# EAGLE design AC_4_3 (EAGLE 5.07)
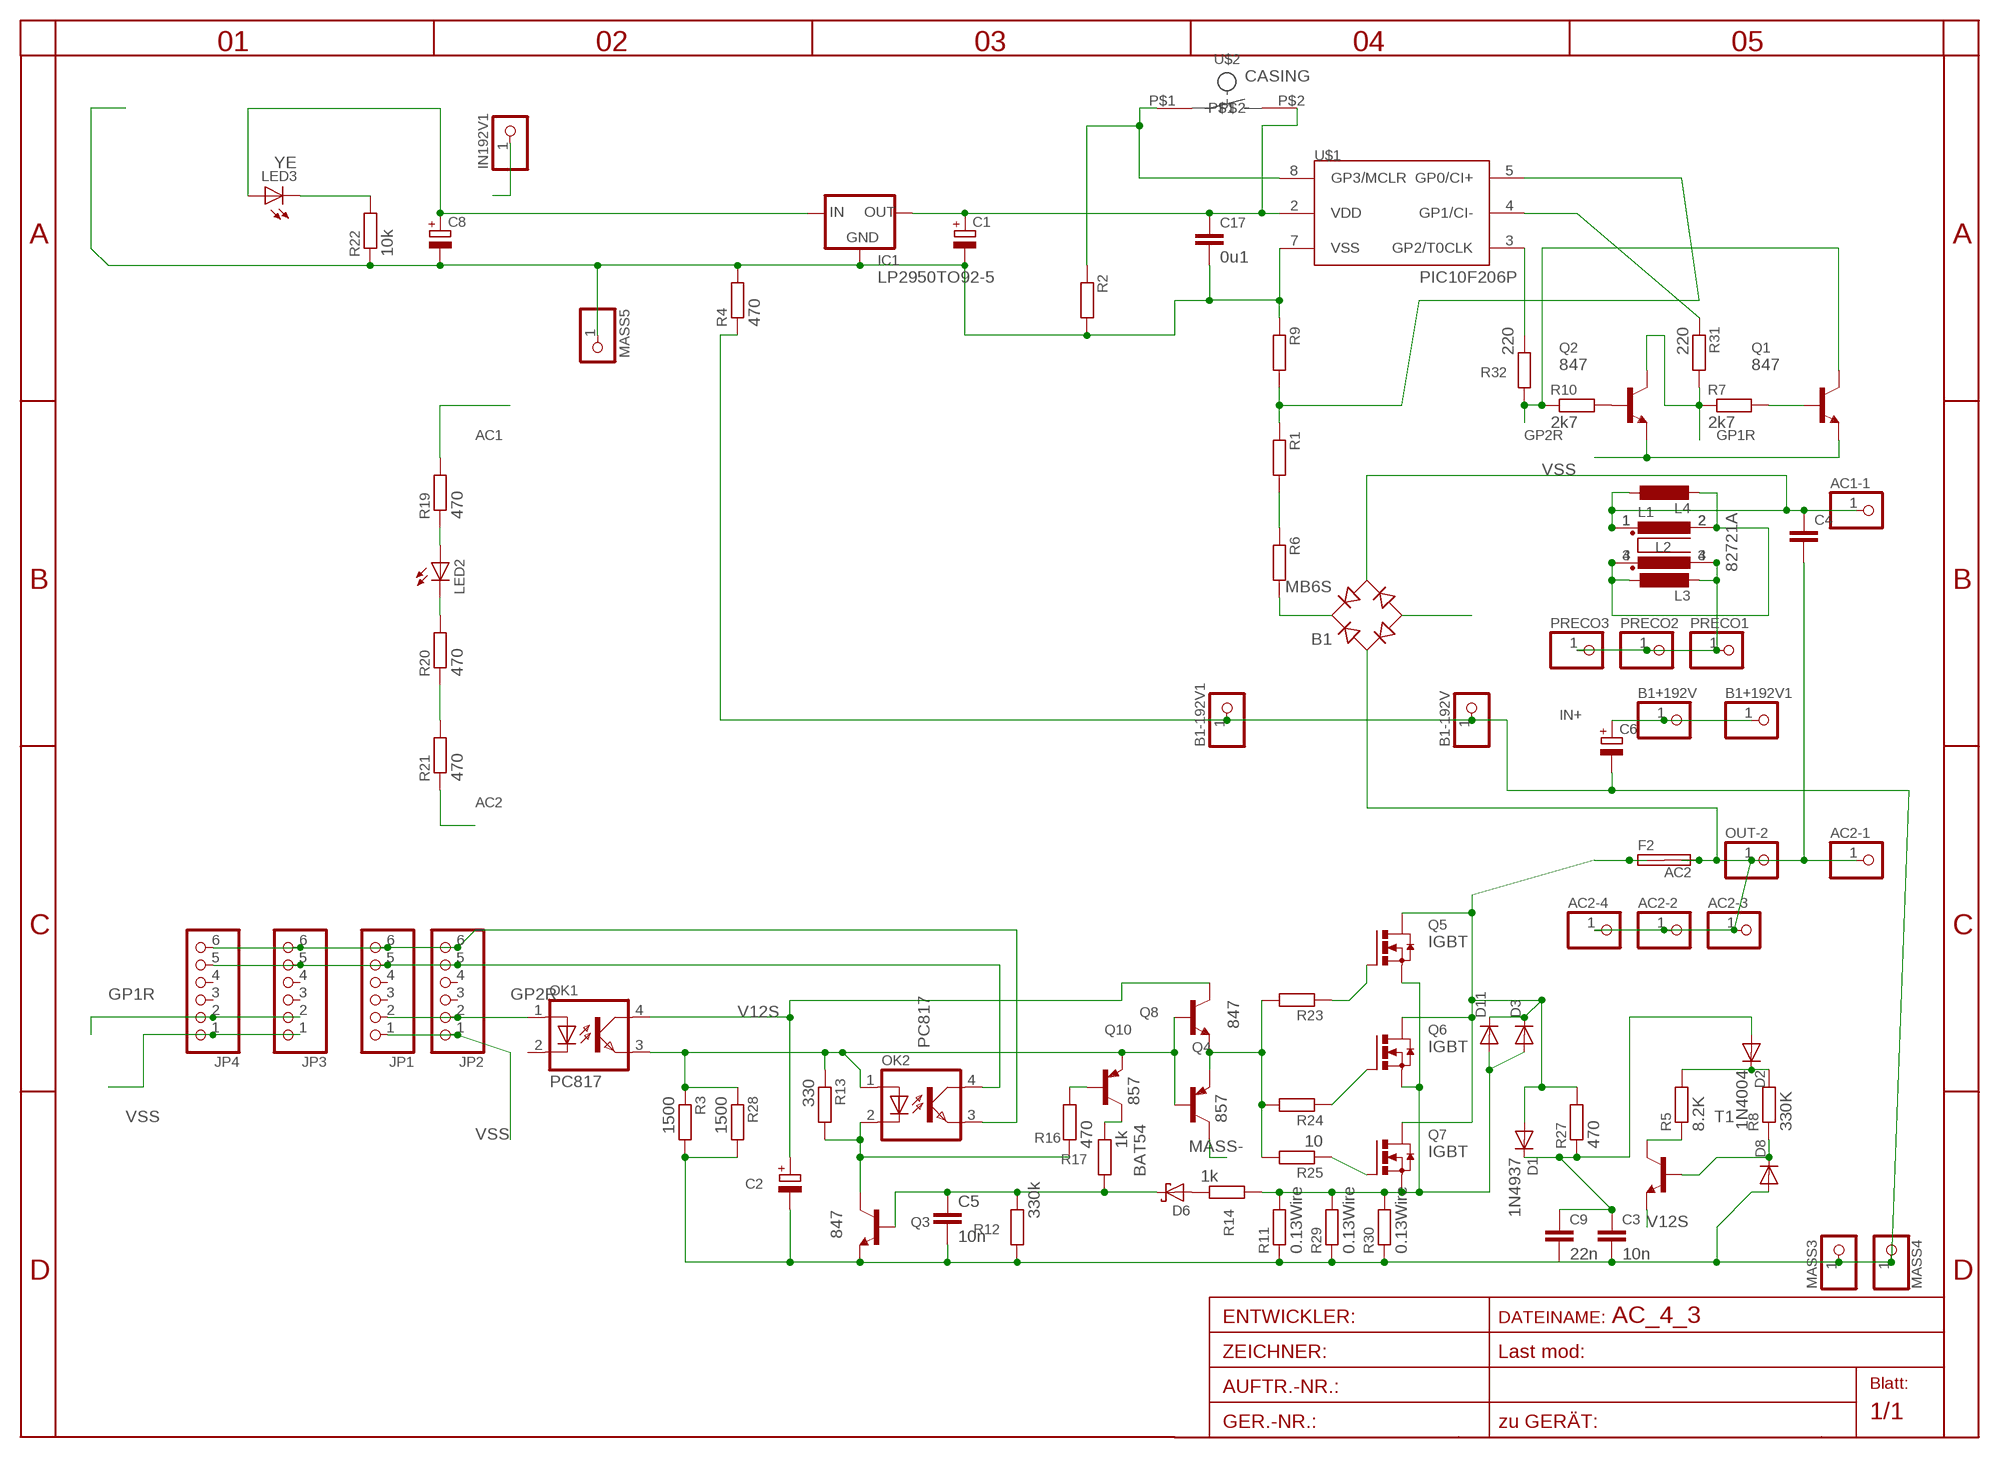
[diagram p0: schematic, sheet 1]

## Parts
AC1-1  PINHD-1X14.5MM  [1X4MM5]
AC2-1  PINHD-1X14.5MM  [1X4MM5]
AC2-2  PINHD-1X13MM2  [1X3MM2]
AC2-3  PINHD-1X13MM2  [1X3MM2]
AC2-4  PINHD-1X12MM3  [1X2MM3]
B1  MB6S  [SOIC-4]
B1+192V  PINHD-1X13MM2  [1X3MM2]
B1+192V1  PINHD-1X13MM2  [1X3MM2]
B1-192V  PINHD-1X13MM2  [1X3MM2]
B1-192V1  PINHD-1X13MM2  [1X3MM2]
C1  CPOL-EUE5-6  [E5-6]
C2  CPOL-EUE2.5-5  [E2,5-5]
C3  10n  C-EU025_050-050X075  [C025_050-050X075]
C4  C-EU225-108X268  [C225-108X268]
C5  10n  C-EUC0805  [C0805]
C6  CPOL-EUE10-20  [EB20D]
C8  CPOL-EUE5-5  [E5-5]
C9  22n  C-EU102-043X133  [C102-043X133]
C17  0u1  C-EUC1206  [C1206]
D1  1N4937  1N4004DO41-10  [DO41-10]
D2  1N4004  [DO41-20]
D3  DIODE-SMC  [SMC]
D6  BAT54  [SOT23]
D8  DIODE-MINIMELF  [MINIMELF]
D11  DIODE-SMC  [SMC]
F2  SHK20L7MM5  [7MM5]
IC1  LP2950TO92-5  [T092-5]
IN192V1  PINHD-1X13MM2  [1X3MM2]
JP1  PINHD-1X6  [1X06BOX]
JP2  PINHD-1X6  [1X06BOX]
JP3  PINHD-1X6  [1X06BOX]
JP4  PINHD-1X6  [1X06BOX]
L1  R1405VB1  [B1]
L2  82721A  [82721A]
L3  L-EU2200-15.24  [2200-15.24]
L4  L-EU2200-15.24  [2200-15.24]
LED2  LED3MM  [LED3MM]
LED3  YE  LEDCHIPLED_1206  [CHIPLED_1206]
MASS3  PINHD-1X13MM2  [1X3MM2]
MASS4  PINHD-1X13MM2  [1X3MM2]
MASS5  PINHD-1X11MM6  [1X1MM8]
OK1  PC817  [DIL04]
OK2  PC817  [DIL04]
OUT-2  PINHD-1X13MM2  [1X3MM2]
PRECO1  PINHD-1X12MM3  [1X2MM3]
PRECO2  PINHD-1X13MM2  [1X3MM2]
PRECO3  PINHD-1X13MM2  [1X3MM2]
Q1  847  BC847ALT1SMD  [SOT23]
Q2  847  BC847ALT1SMD  [SOT23]
Q3  847  BC846ALT1SMD  [SOT23]
Q4  857  BC857ALT1SMD  [SOT23-BEC]
Q5  IGBT  N-HEXFET_DPAK-  [TO252]
Q6  IGBT  N-HEXFET_DPAK-  [TO252]
Q7  IGBT  N-HEXFET_DPAK-  [TO252]
Q8  847  BC846ALT1SMD  [SOT23]
Q10  857  BC857ALT1SMD  [SOT23-BEC]
R1  R-EU_0207/30  [0207/30]
R2  R-EU_R0805  [R0805]
R3  1500  R-EU_R0805  [R0805]
R4  470  R-EU_0204/5  [0204/5]
R5  8.2K  R-EU_0204/5  [0204/5]
R6  R-EU_0207/50  [0207/50]
R7  2k7  R-EU_R0805  [R0805]
R8  330K  R-EU_0204/5  [0204/5]
R9  R-EU_R0805  [R0805]
R10  2k7  R-EU_R0805  [R0805]
R11  0.13Wire  R-EU_0204/5  [0204/5]
R12  330k  R-EU_R0805  [R0805]
R13  330  R-EU_R1206  [R1206]
R14  1k  R-EU_R0805  [R0805]
R16  470  R-EU_R0805  [R0805]
R17  1k  R-EU_R0805  [R0805]
R19  470  R-EU_0204/5  [0204/5]
R20  470  R-EU_0204/2V  [0204V]
R21  470  R-EU_0204/5  [0204/5]
R22  10k  R-EU_R1206  [R1206]
R23  R-EU_0207/15  [0207/15]
R24  R-EU_0207/10  [0207/10]
R25  10  R-EU_0207/15  [0207/15]
R27  470  R-EU_0207/10  [0207/10]
R28  1500  R-EU_R1206  [R1206]
R29  0.13Wire  R-EU_0204/5  [0204/5]
R30  0.13Wire  R-EU_0204/5  [0204/5]
R31  220  R-EU_R1206  [R1206]
R32  220  R-EU_R1206  [R1206]
T1  -NPN-TO92-EBC  [TO92-EBC]
U$1  PIC10F206P  [DIL8]
U$2  CASING  [CASING]

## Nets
AC1: AC1-1.1 B1.~2(AC2) C4.1 L1.1 L2.1 L4.1 R19.2
AC2: AC2-1.1 AC2-2.1 AC2-3.1 AC2-4.1 B1.~1(AC1) C4.2 F2.2A F2.2B OUT-2.1 R21.1
BATT+: C8.+ IC1.3(IN) LED3.A
D1: D1.A D3.C D11.C F2.1A F2.1B Q5.3(D) Q6.3(D) Q7.3(D) R27.2
GP1R: JP3.2 JP4.2 Q2.3(C) R7.1 R31.2
GP2R: JP1.2 JP2.2 OK1.1(A) Q1.3(C) R10.1 R32.2
GP3: JP1.6 JP2.6 JP3.6 JP4.6 OK2.3(EMIT) R2.1 U$1.8(GP3/MCLR) U$2.P$1
IN+: B1+192V1.1 B1+192V.1 C6.+ IN192V1.1
INN: L1.2 L1.3 L2.2 L2.4 L3.1 L4.2
MASS-: B1-192V1.1 B1-192V.1 B1.- C2.- C3.3 C5.2 C6.- C9.2 D8.A MASS3.1 MASS4.1 Q3.2(E) Q4.C R3.2 R4.1 R11.1 R12.2 R28.2 R29.1 R30.1
N$1: R1.1 R9.2 U$1.5(GP0/CI+)
N$2: C3.1 C9.1 D1.C D2.A R27.1
N$3: R1.2 R6.1
N$4: Q2.1(B) R10.2
N$6: LED2.A R19.1
N$7: Q1.1(B) R7.2
N$9: LED2.K(C) R20.2
N$11: C5.1 D6.3(C) Q3.1(B) R12.1 R17.2
N$12: OK2.2(C) Q3.3(C) R13.2 R16.1
N$13: R20.1 R21.2
N$14: D6.1(A) R14.1
N$15: LED3.C R22.2
N$16: Q10.B R16.2
N$17: Q10.C R17.1
N$20: D2.C R5.2 R8.2
N$25: Q7.1(G) R25.1
N$26: Q6.1(G) R24.1
N$27: Q5.1(G) R23.1
N$33: B1.+ R6.2
N$34: R5.1 T1.C
N$36: D8.C R8.1 T1.B
N$37: Q4.E Q8.2(E) R23.2 R24.2 R25.2
N$39: R31.1 U$1.4(GP1/CI-)
N$43: R32.1 U$1.3(GP2/T0CLK)
PP1: OK1.3(EMIT) OK2.1(A) Q4.B Q8.1(B) Q10.E R3.1 R13.1 R28.1
PRECOIL: L1.4 L2.3 L3.2 PRECO1.1 PRECO2.1 PRECO3.1
SRC1: D3.A D11.A Q5.2(S) Q6.2(S) Q7.2(S) R11.2 R14.2 R29.2 R30.2
V12S: C2.+ OK1.4(COL) Q8.3(C) T1.E
VDD: C1.+ C17.1 IC1.1(OUT) JP1.5 JP2.5 JP3.5 JP4.5 OK2.4(COL) U$1.2(VDD) U$2.P$2
VSS: C1.- C8.- C17.2 IC1.2(GND) JP1.1 JP2.1 JP3.1 JP4.1 MASS5.1 Q1.2(E) Q2.2(E) R2.2 R4.2 R9.1 R22.1 U$1.7(VSS)
Unconnected: JP1.3 JP1.4 JP2.3 JP2.4 JP3.3 JP3.4 JP4.3 JP4.4 OK1.2(C)

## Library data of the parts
AC1-1 AC2-1-AC2-4 B1+192V B1+192V1 B1-192V B1-192V1 IN192V1 MASS3-MASS5 OUT-2 PRECO1-PRECO3 = pinhead:PINHD-1X1: PIN HEADER
B1 = rectifier:MB*S: Bridge Rectifier Source: http://www.fairchildsemi.com/ds/MB/MB6S.pdf
C1 C2 C8 = rcl-2:CPOL-EU: POLARIZED CAPACITOR, European symbol
C3 C9 C17 = rcl-2:C-EU: CAPACITOR, European symbol
C4 C5 = rcl:C-EU: CAPACITOR, European symbol
C6 = rcl:CPOL-EU: POLARIZED CAPACITOR, European symbol
D1 D2 = diode:1N4004: DIODE
D3 D8 D11 = diode:DIODE-: DIODE
D6 = diode:BAT54: Schottky Diodes
F2 = fuse:SHK20L: FUSE HOLDER 5 x 20 mm, SH contact, SHH1 Schukat, E1073 Buerklin
IC1 = v-reg:LP2950?*: Source: http://cache.national.com/ds/LP/LP2950.pdf
JP1-JP4 = pinhead:PINHD-1X6: PIN HEADER
L1 = inductor-nkl:R1405V: Übertrager (verlustarm) bis typ. 400kHz Power transformer (low loss) up to typ. 400kHz
L2 = inductors:82721A: FILTER
L3 L4 = rcl:L-EU: INDUCTOR, European symbol
LED2 LED3 = led:LED: LED
OK1 OK2 = optocoupler:PC817: SHARP OPTO COUPLER
Q1 Q2 = transistor-npn:BC847*: NPN Transistor
Q3 Q8 = transistor-npn:BC846*: NPN Transistor
Q4 Q10 = transistor-pnp:BC857*: PNP Transistror
Q5-Q7 = transistor-power:N-HEXFET_?-*: HEXFET® Power MOSFET
R1-R14 R16 R17 R19-R25 R27-R32 = rcl-2:R-EU_: RESISTOR, European symbol
T1 = transistor-neu-to92:*-NPN-: NPN Transistror
U$1 = microchip-5:PIC10F2*: uPC nW 0,25/0,5k Program Flash memory Comparator
U$2 = button:CASING

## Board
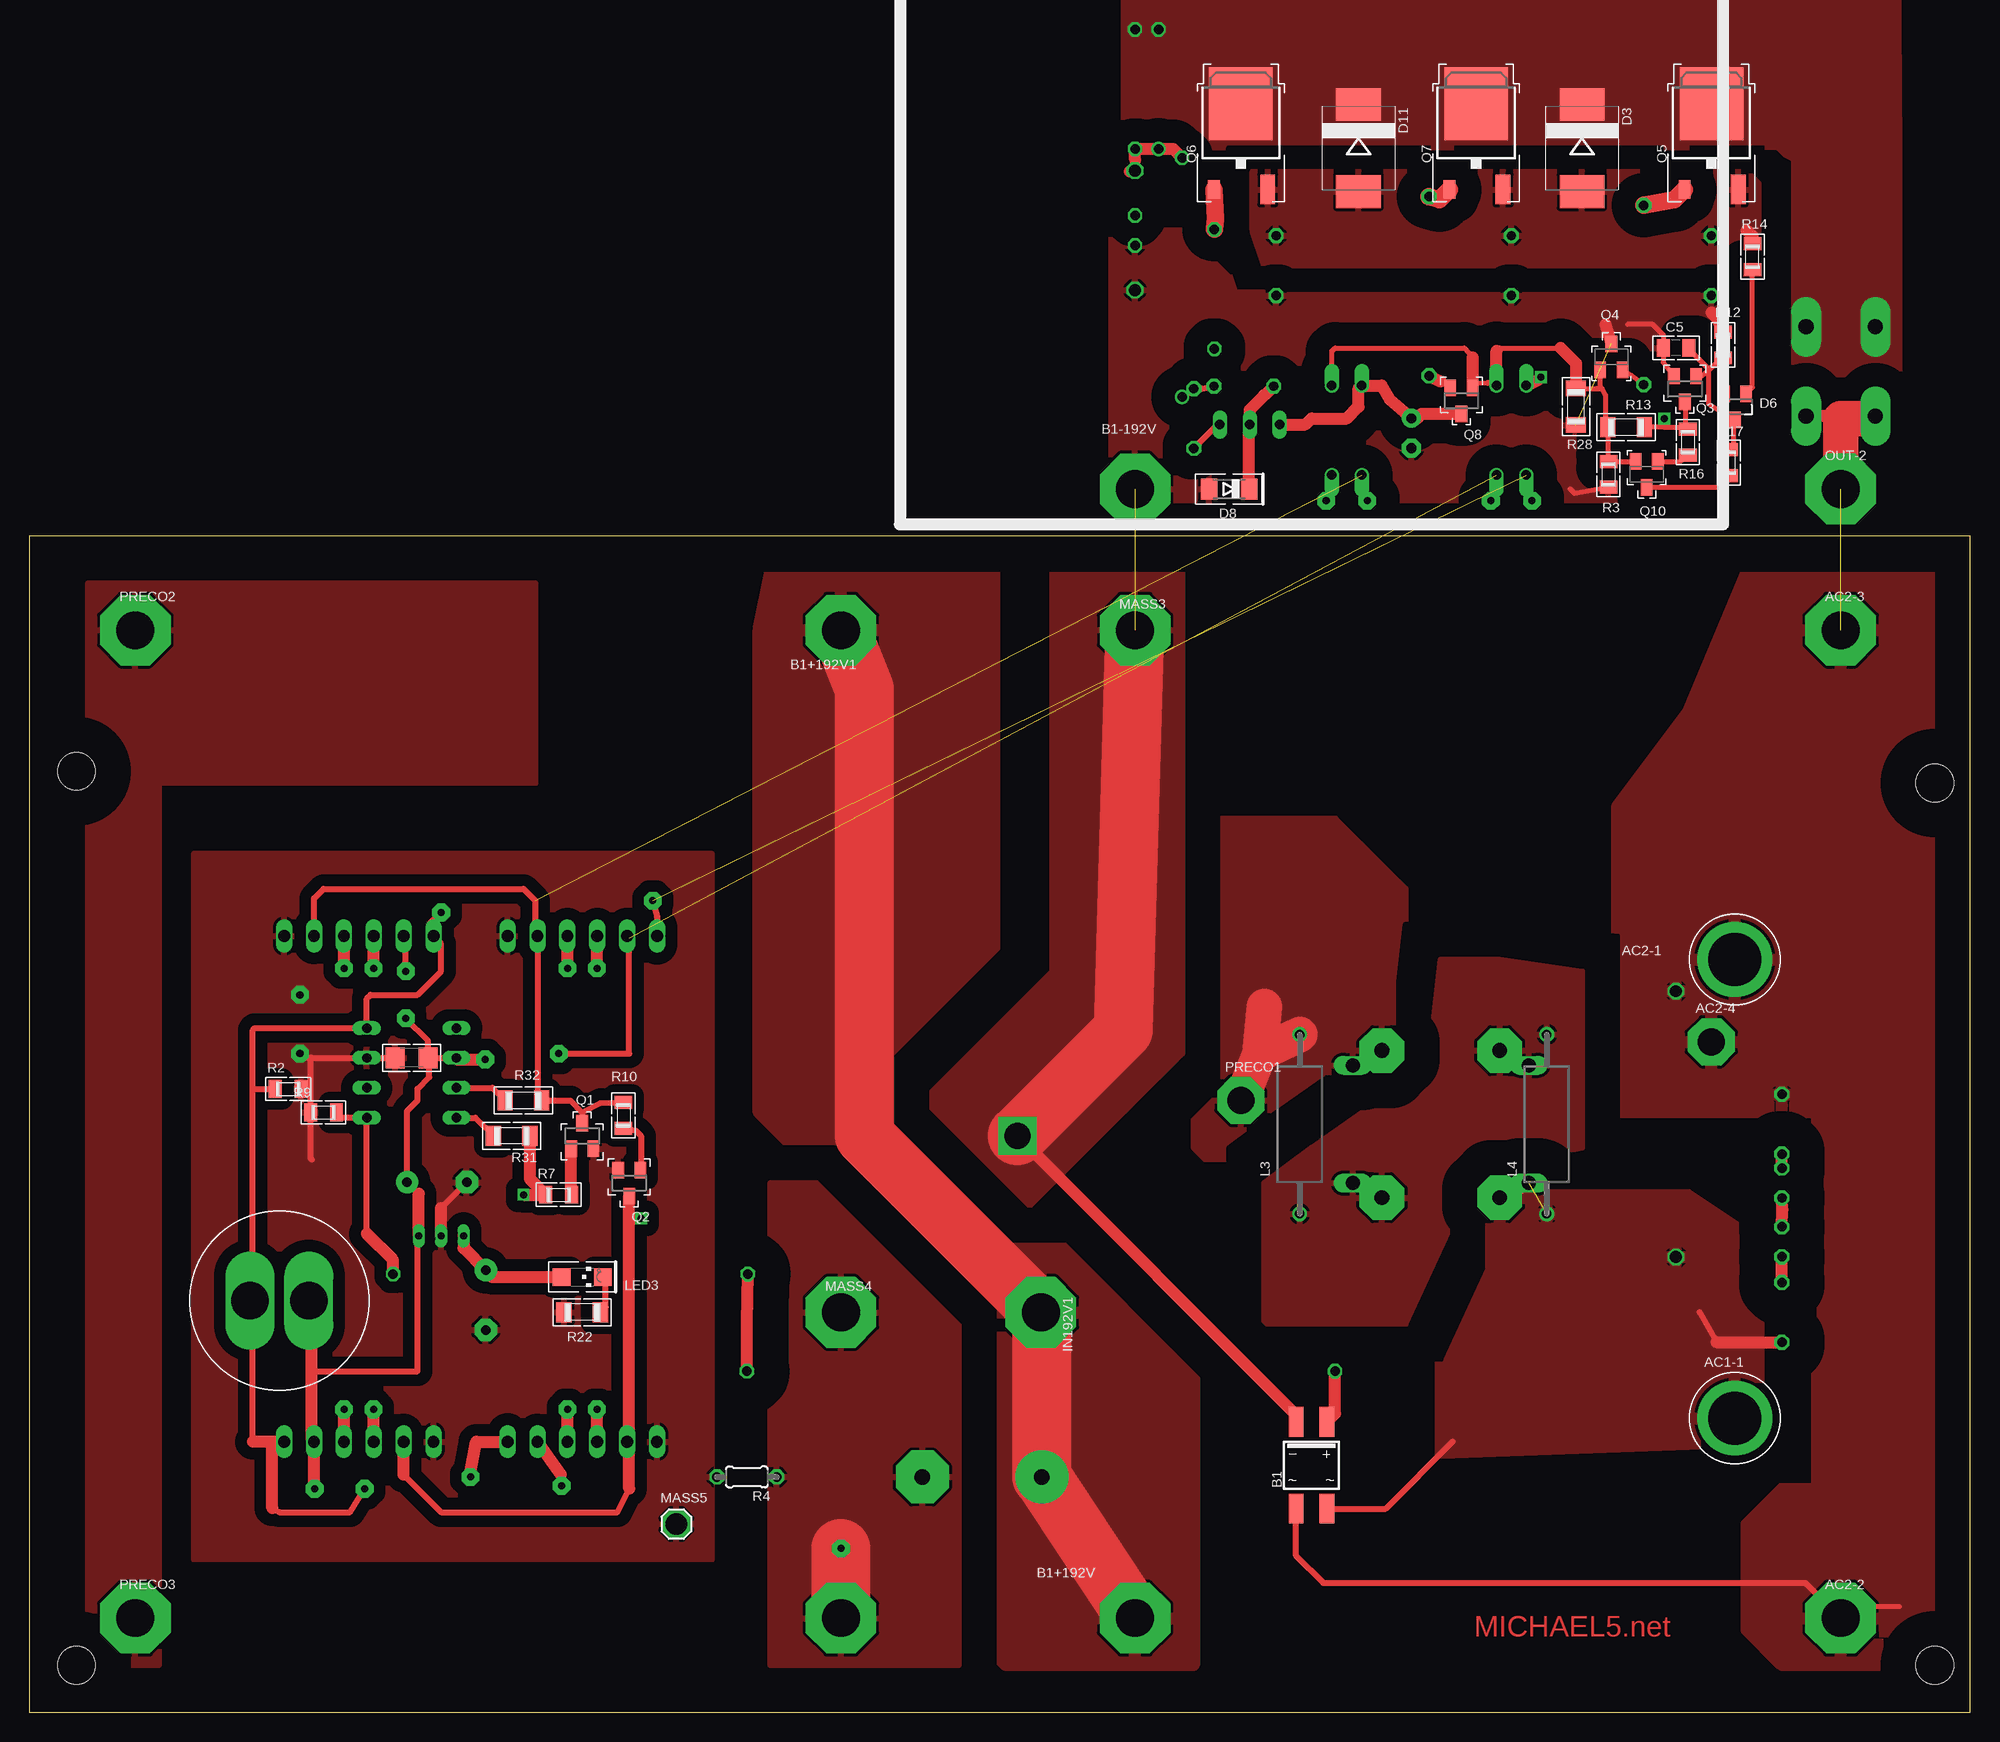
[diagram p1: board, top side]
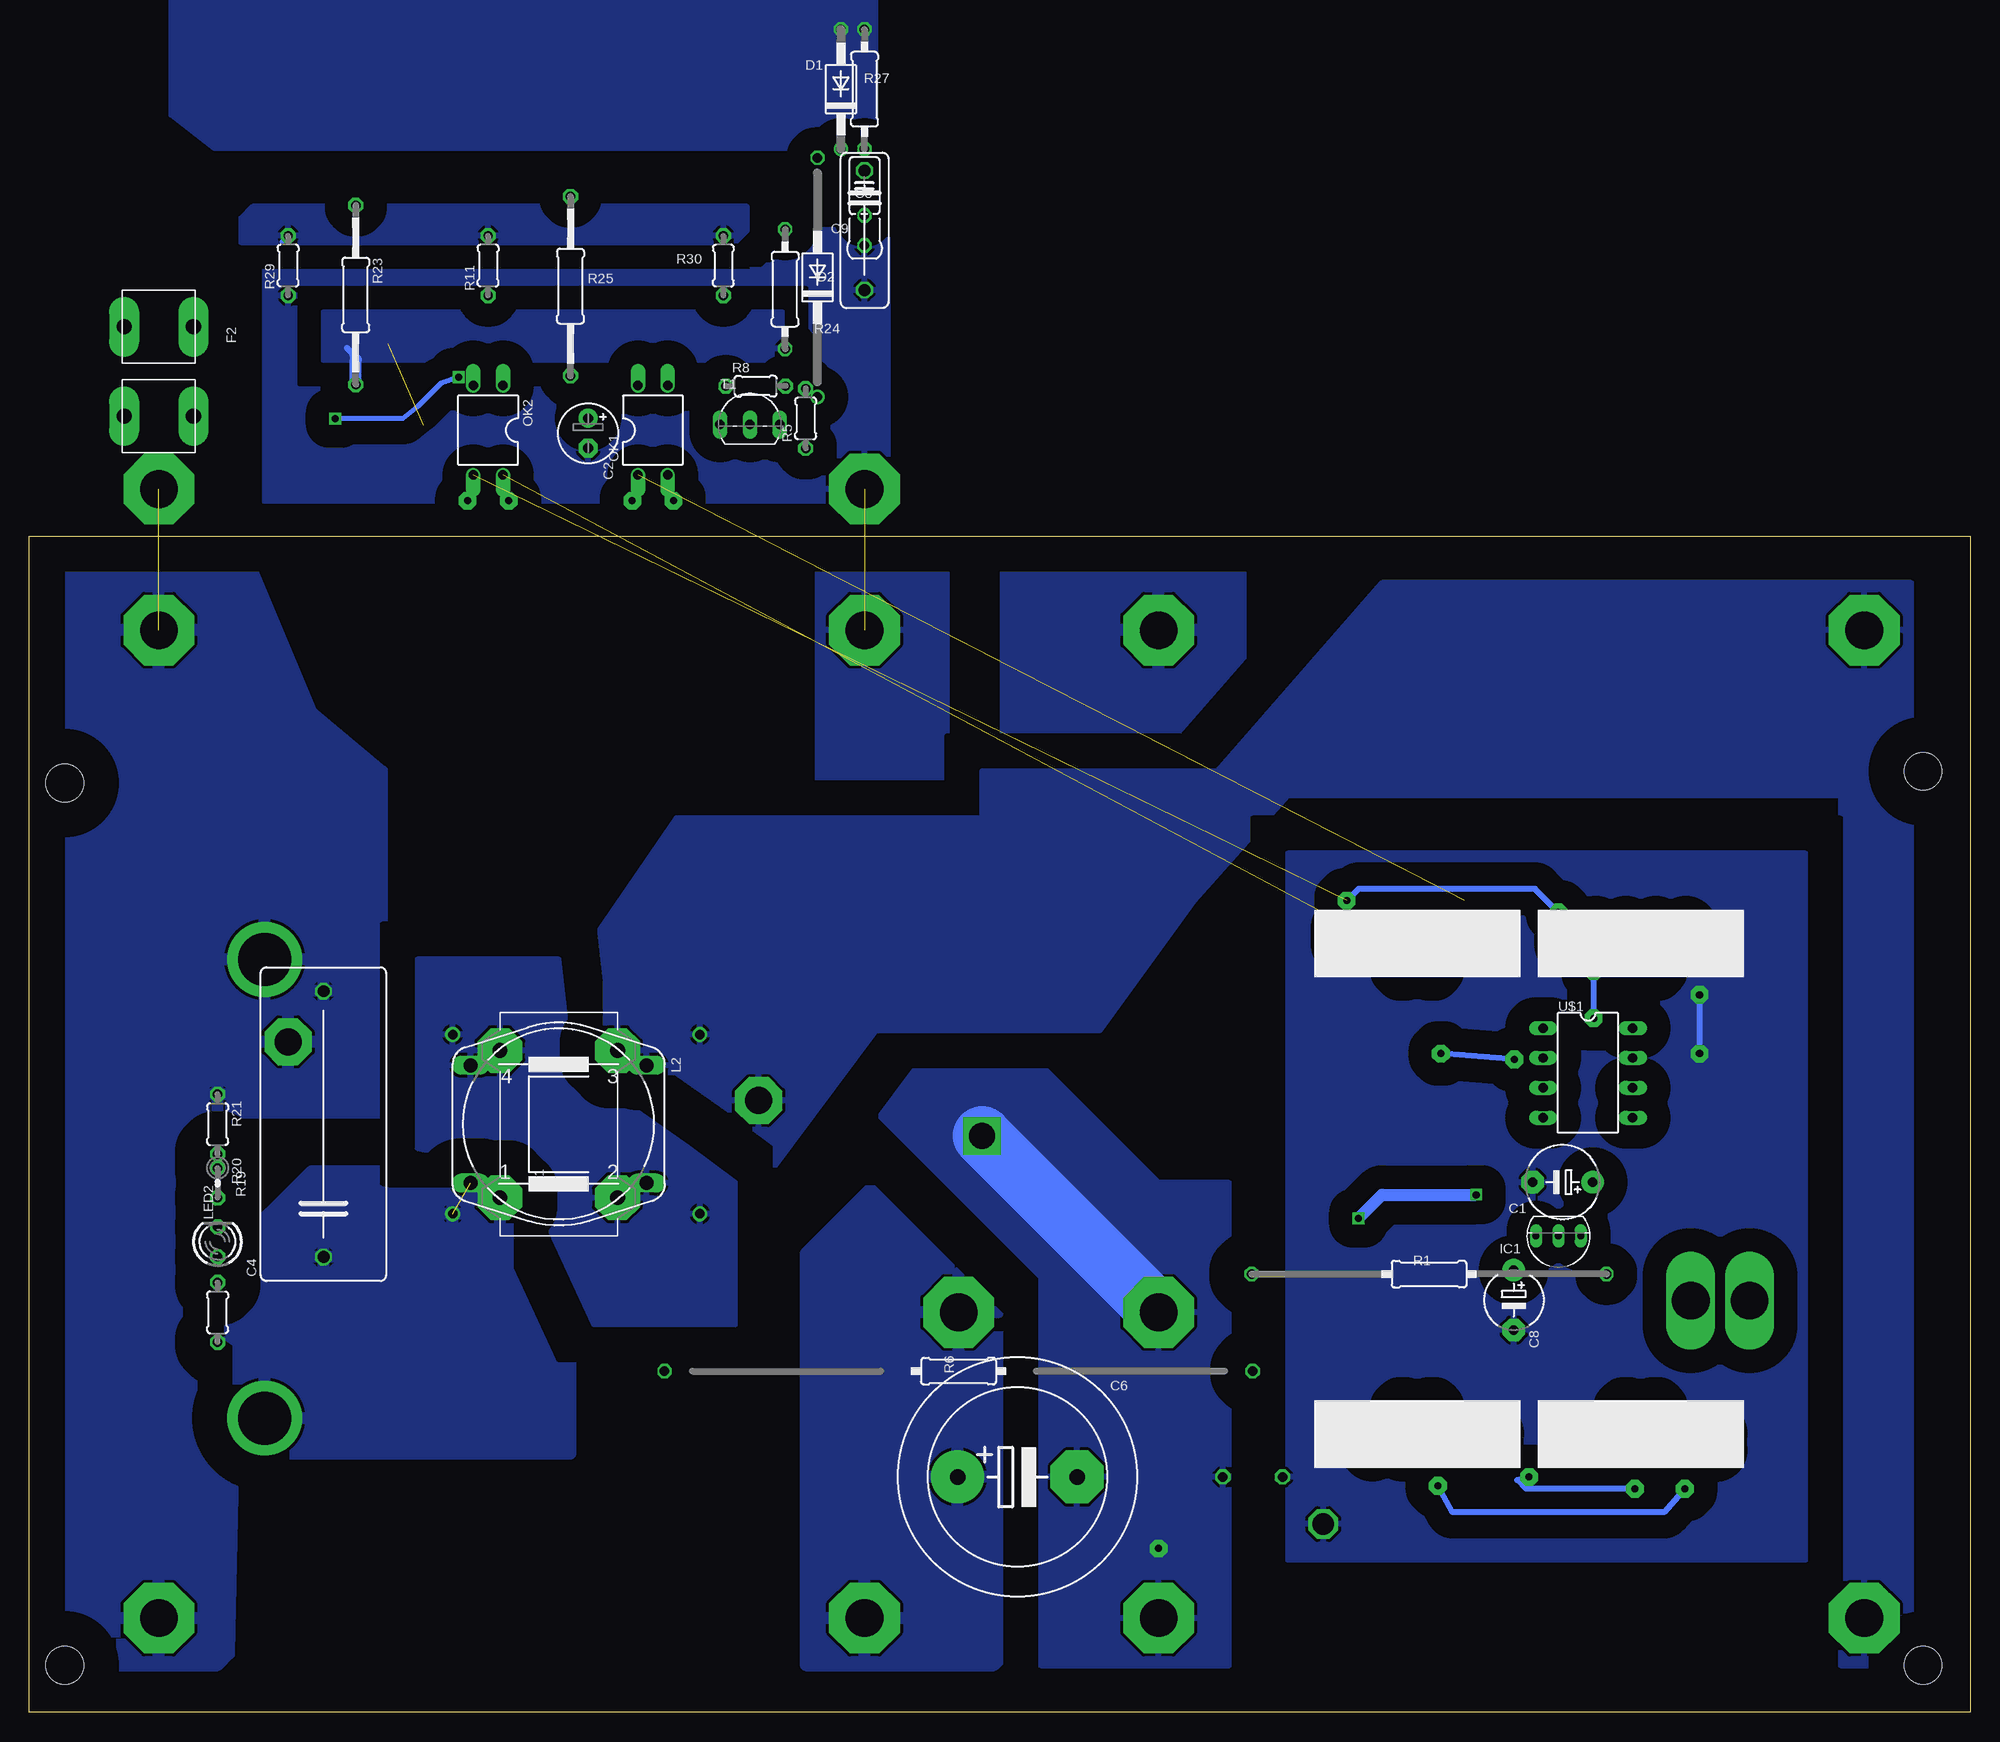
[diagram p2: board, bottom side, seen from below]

Size 165 x 100 mm. Coordinates in mm from the lower left corner, seen from the top.
Outline: 0,0 165,0 165,100 0,100 0,0
Copper layers (1*16): Top 0.035mm / dielectric 1.5mm / Bottom 0.035mm
Design rules "default *": minimum track width 12mil, minimum drill 24mil, track to track 8mil, track to pad 8mil, pad to pad 8mil, via to via 8mil, smd to smd 8mil, copper to edge 40mil, drill to drill 8mil, minimum pad ring 8mil, minimum via ring 8mil, stop-mask expansion 4mil, vias tented up to drill 0mil, thermal gap 10mil
Holes 3.2 mm at 4,80 4,4 162,79 162,4

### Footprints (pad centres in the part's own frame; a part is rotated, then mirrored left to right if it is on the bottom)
1X4MM5 = drill 4.5 pad 6.35 round: 1 0,0
1X3MM2 = drill 3.2 pad 6 octagon: 1 0,0
1X2MM3 = drill 2.3 pad 4 octagon: 1 0,0
SOIC-4 = smd 1.27 x 2.54: + 1.3,3.685; - -1.3,3.685; ~1 -1.3,-3.685; ~2 1.3,-3.685
E5-6 = drill 0.813 pad 1.905 round: + -2.54,0 | drill 0.813 pad 1.905 octagon: - 2.54,0
E2,5-5 = drill 0.813 pad 1.6 round: + -1.27,0 | drill 0.813 pad 1.6 octagon: - 1.27,0
C025_050-050X075 = drill 0.813 octagon: 1 -3.81,0; 2 0,0; 3 2.54,0
C225-108X268 = drill 1.016 octagon: 1 -11.303,0; 2 11.303,0
C0805 = smd 1.1 x 1.5: 1 -1.1,0; 2 1.1,0
EB20D = drill 1.3 pad 4.5 round: + -5.08,0 | drill 1.3 pad 4.5 octagon: - 5.08,0
E5-5 = drill 0.813 pad 1.905 round: + -2.54,0 | drill 0.813 pad 1.905 octagon: - 2.54,0
C102-043X133 = drill 1.016 octagon: 1 -5.08,0; 2 5.08,0
C1206 = smd 1.6 x 1.8: 1 -1.4,0; 2 1.4,0
DO41-10 = drill 0.8 octagon: A 5.08,0 | drill 0.8 round: C -5.08,0
DO41-20 = drill 0.8 octagon: A 10.16,0 | drill 0.8 round: C -10.16,0
SMC = smd 2.8 x 3.8: A 3.7,0; C -3.7,0
SOT23 = smd 1 x 1.4: 1 -0.95,-1.1; 2 0.95,-1.1; 3 0,1.1
MINIMELF = smd 1.4 x 1.8: A 1.7,0; C -1.7,0
7MM5 = drill 1.3 pad 2.54 long: 1A -3.8,2.94; 1B -3.8,-2.94; 2A 3.8,2.94; 2B 3.8,-2.94
T092-5 = drill 0.6 pad 0.813 long: 1 -1.905,0; 2 0,0; 3 1.905,0
1X06BOX = drill 1 long: 1 -6.35,0; 2 -3.81,0; 3 -1.27,0; 4 1.27,0; 5 3.81,0 | drill 1.016 long: 6 6.35,0
B1 = drill 1.27 pad 3.81 octagon: 1 -6.25,5; 2 -6.25,-5; 3 6.25,5; 4 6.25,-5
82721A = drill 1.194 long: 1 7.493,5.004; 2 -7.493,5.004; 3 -7.493,-5.004; 4 7.493,-5.004
2200-15.24 = drill 0.8 pad 1.27 round: 1 -7.62,0; 2 7.62,0
LED3MM = drill 0.8 pad 1.27 octagon: A -1.27,0; K 1.27,0
CHIPLED_1206 = smd 1.5 x 1.5: A 0,-1.75; C 0,1.75
1X1MM8 = drill 1.8 pad 2.54 octagon: 1 0,0
DIL04 = drill 0.813 offset: 1 -1.27,-3.81; 2 1.27,-3.81; 3 1.27,3.81; 4 -1.27,3.81
SOT23-BEC = smd 1 x 1.4: B -0.95,-1.1; C 0,1.1; E 0.95,-1.1
TO252 = smd 1 x 1.6: 1 -2.28,-3.53 | smd 1.27 x 2.54: 2 2.28,-3.53 | smd 5.4 x 6.2: 3 0,3.77
0207/30 = drill 0.813 octagon: 1 -15.08,0; 2 15.08,0
R0805 = smd 1.1 x 1.5: 1 -1.1,0; 2 1.1,0
0204/5 = drill 0.8 pad 1.27 octagon: 1 -2.54,0; 2 2.54,0
0207/50 = drill 0.813 octagon: 1 -25,0; 2 25,0
R1206 = smd 1.3 x 1.7: 1 -1.55,0; 2 1.55,0
0204V = drill 0.8 pad 1.27 octagon: 1 -1.27,0; 2 1.27,0
0207/15 = drill 0.8 pad 1.27 octagon: 1 -7.62,0; 2 7.62,0
0207/10 = drill 0.813 octagon: 1 -5.08,0; 2 5.08,0
TO92-EBC = drill 0.813 long: B 0,-1.27; C 2.54,-1.27; E -2.54,-1.27
DIL8 = drill 0.8 long: 1 -3.81,-3.81; 2 -1.27,-3.81; 3 1.27,-3.81; 4 3.81,-3.81; 5 3.81,3.81; 6 1.27,3.81; 7 -1.27,3.81; 8 -3.81,3.81
CASING = drill 3.2 pad 3.81 long: P$1 -2.5,0; P$2 2.5,0

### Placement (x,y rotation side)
AC1-1  145,25 0 top
AC2-1  145,64 0 top
AC2-2  154,8 0 top
AC2-3  154,92 0 top
AC2-4  143,57 0 top
B1  109,21 0 top
B1+192V  94,8 0 top
B1+192V1  69,92 180 top
B1-192V  not placed on the board
B1-192V1  69,8 0 top
C1  34.65,45.07 180 bottom
C2  117.5,108.75 270 bottom  (outside the outline)
C3  94,127.25 270 bottom  (outside the outline)
C4  140,50 90 bottom
C5  140,116 180 top  (outside the outline)
C6  81,20 0 bottom
C8  38.8,35.05 270 bottom
C9  94,126 270 bottom  (outside the outline)
C17  32.49,55.63 180 top
D1  96,138 90 bottom  (outside the outline)
D2  98,122 90 bottom  (outside the outline)
D3  not placed on the board
D6  145,111 180 top  (outside the outline)
D8  102,104 180 top  (outside the outline)
D11  not placed on the board
F2  154,114 270 bottom  (outside the outline)
IC1  35,40.5 180 bottom
IN192V1  86,34 270 top
JP1  47,66 180 bottom
JP2  28,66 180 bottom
JP3  28,23 0 bottom
JP4  47,23 0 bottom
L1  120,50 90 bottom
L2  120,50 180 bottom
L3  108,50 90 top
L4  129,50 90 top
LED2  149,40 90 bottom
LED3  47,37 270 top
MASS3  94,92 0 top
MASS4  69,34 0 top
MASS5  55,16 0 top
OK1  112,109 0 bottom  (outside the outline)
OK2  126,109 180 bottom  (outside the outline)
OUT-2  154,104 0 top  (outside the outline)
PRECO1  103,52 0 top
PRECO2  9,92 0 top
PRECO3  9,8 0 top
Q1  47,49 0 top
Q2  51,45 180 top
Q3  140.75,112.5 180 top  (outside the outline)
Q4  134.5,115.25 0 top  (outside the outline)
Q5  143,133 0 top  (outside the outline)
Q6  103,133 0 top  (outside the outline)
Q7  123,133 0 top  (outside the outline)
Q8  121.75,111.5 180 top  (outside the outline)
Q10  137.5,105.25 180 top  (outside the outline)
R1  46,37.25 180 bottom
R2  22,53 0 top
R3  134.25,105.25 270 top  (outside the outline)
R4  61,20 180 top
R5  99,110 90 bottom  (outside the outline)
R6  86,29 180 bottom
R7  45,44 0 top
R8  103.25,112.75 0 bottom  (outside the outline)
R9  25,51 0 top
R10  50.5,50.75 270 top
R11  not placed on the board
R12  144,116.25 90 top  (outside the outline)
R13  135.75,109.25 0 top  (outside the outline)
R14  146.5,123.75 90 top  (outside the outline)
R16  141,108 270 top  (outside the outline)
R17  144.5,106.25 90 top  (outside the outline)
R19  149,34 270 bottom
R20  149,45 270 bottom
R21  149,50 270 bottom
R22  47,34 0 top
R23  137.25,120.5 270 bottom  (outside the outline)
R24  100.75,121 270 bottom  (outside the outline)
R25  119,121.25 270 bottom  (outside the outline)
R27  94,138 90 bottom  (outside the outline)
R28  131.5,111 270 top  (outside the outline)
R29  143,123 90 bottom  (outside the outline)
R30  not placed on the board
R31  41,49 0 top
R32  42,52 0 top
T1  103.75,110.75 0 bottom  (outside the outline)
U$1  32.49,54.36 270 bottom
U$2  21.25,35 0 top

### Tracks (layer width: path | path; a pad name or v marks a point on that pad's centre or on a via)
AC1  (1 unrouted)
  Top 0.5: 142,34 143.46,31.46 | B1.~2 115.31,17.32 121,23 | L1.1 126.25,43.75 L2.1
  Top 1: 143.46,31.46 R19.2
  pour Top (isolate 3, rank 3): 120,44 141,44 147,40 147,23 120,22
  pour Bottom (isolate 3, rank 3): 119,46 141,46 148,39 148,22 119,22
AC2  (1 unrouted)
  Top 0.406: 159,9 155,9 AC2-2.1
  Top 0.5: B1.~1 107.7,13.3 110,11 151,11 AC2-2.1
  Top 1: F2.2A F2.2B 156.74,110 156,110
  Top 3: OUT-2.1 154,110 156,110
  pour Top (isolate 3, rank 2): 146,97 162,97 163,84 163,8 159,4 149,4 146,7 146,16 149,19 152,19 152,51 135,51 135,77 141,85
  pour Bottom (isolate 3, rank 2): 146,97 162,97 163,84 163,8 159,4 149,4 148,5 147,51 135,51 135,80 141,85
BATT+
  Top 1: IC1.3 36.91,39.48 C8.+ 39.38,37 LED3.A
D1
  pour Top (isolate 2, rank 2, no thermals): 93,149 158.89,149 159,133 159,112 150,112 150,132 148,133 93,133
  pour Bottom (isolate 2, rank 2, no thermals): 93,149 153,149 153,135.82 149.35,133 93,133
GP1R  (via drill 0.6)
  Top 0.5: 31.81,20.19 35,17 50,17 51,19 | 51,22.81 JP4.2
  Top 1: 51,19 51,22.81 | 31.81,20.19 JP3.2 | R31.2 42.55,45.35 R7.1 v42,44 | 51,42 51,23.19 JP4.2 | 51,42 Q2.3 | 51,42 v52,42
  Bottom 1: v42,44 50,44 v52,42
GP2R  (1 unrouted)
  Top 0.5: R10.1 48.55,51.8 47,51 | 47,51 Q1.3 | 47,51 46,52 R32.2 43.19,52.36 JP1.2 43,66.19 43,69 42,70 25,70 24.19,69.19 JP2.2
GP3  (via drill 0.6 pad 1.5)  (1 unrouted)
  Top 0.5: 20.65,17.35 21.25,17 27.25,17 v28.5,19 | 19,23 19,31.5 U$2.P$1 19,36.5 19,53 | 19,53 R2.1 | 19,53 19,58 19.17,58.17 U$1.8 28.68,60.68 29,61 33,61 35,63 35,65.35 JP2.6 34,66.35 34,67 v35,68 | 20.65,22.65 21,23 | v37.5,20 37.5,20.5 | JP1.6 53.35,67.65 v53,69
  Top 1: 19,23 JP3.6 21,23 | 20.65,17.35 20.65,22.65 | 37.5,20.5 38,23 JP4.6
  Bottom 0.5: v28.5,19 37.75,19 38.5,19.75 v37.5,20 | v53,69 52,70 37,70 v35,68
IN+
  Top 5: B1+192V.1 94.08,7.92 C6.+ 86.08,31.92 IN192V1.1 71,49 71,87 B1+192V1.1
  pour Top (isolate 3, rank 5): 63,97 82,97 82,56 99,39 99,4 83,4 81,6 81,32 62,51 62,52 62,92
  pour Bottom (isolate 3, rank 5): 62,97 82,97 82,56 99,39 99,4 83,4 81,6 81,32 62,51
INN
  pour Top (isolate 3): 120,64 125,64 132,63 132,48 123,46 117,33 105,33 105,45 109,48 119,55
  pour Bottom (isolate 3): 120,64 132,64 132,48 123,46 117,33 105,33 105,45 109,48 119,55
MASS-  (via drill 0.6 pad 1.5, 2.2 pad 3)  (2 unrouted)
  Top 0.406: R3.2 131.35,103.65 131,104 | Q3.2 138.9,114.75 C5.2 138.9,117.1 138,118 135.9,118
  Top 1: R12.2 143.5,118.5 143,119 | Q4.C 134,118 | B1.- 107.7,25.3 v84,49
  Top 5: B1-192V1.1 v69,13.92 | MASS3.1 93,58 v84,49
  Bottom 5: MASS4.1 v84,49
  pour Top (isolate 2, rank 3): 92,126 98,126 102,122 145,122 145,103 92,103
  pour Bottom (isolate 2, rank 3): 92,126 98,126 102,123 145,123 145,103 92,103
  pour Top (isolate 3, rank 3): 87,99 98,98 98,56 79,37 79,4 63,4 63,45 69,45 87,63
  pour Bottom (isolate 3, rank 4): 87,99 98,98 98,56 79,37 79,4 63,4 63,45 69,45 87,63
N$1
  Top 0.5: 28.68,40.68 U$1.5 26.55,50.55 R9.2
  Top 1: R1.1 30.92,38.44 28.68,40.68
N$2
  Top 0.5: 94,132 C9.1 C3.1
  Top 1: 94,132 R27.1 D1.C 97.24,132.92 D2.A | 93.54,131 C9.1
N$3
  Top 1: R6.1 61,33.17 R1.2
N$4
  Top 0.5: R10.2 51.55,49.45 52,49 52,46.15 Q2.1
N$5  (via drill 0.6 pad 1.5)
  Top 1: 48.25,23 v48.25,25.75
N$6
  Top 1.016: R19.1 LED2.A
N$7
  Top 1: Q1.1 46.05,44.05 R7.2
N$8  (via drill 0.6 pad 1.5)
  other vias: 45.75,25.75
N$9
  Top 1.016: R20.2 149.04,42.73 LED2.K
N$10  (via drill 0.6 pad 1.5)
  other vias: 26.75,25.75
N$11
  Top 0.406: 144.85,109.9 D6.3 | 144.85,109.9 142.75,111.25 142.75,114.25 | 142.75,114.25 143,114.4 R12.1 142.2,113.6 Q3.1 | 144.85,109.9 144.85,107.75 R17.2 | C5.1 141.1,115.9 142.75,114.25
N$12  (via drill 0.6)
  Top 0.406: 139,109.25 R13.2 | 139,109.25 140.85,109.25 | 140.85,109.25 R16.1 | 140.85,109.25 140.85,111.25 Q3.3 | 128.31,113.31 v128.5,113.5 | v139,110 139,109.25
  Top 1: OK2.2 128.31,113.31
  Bottom 0.406: v128.5,113.5 130,113 132,111 133.25,110 v139,110
N$13
  Top 1.016: R20.1 R21.2
N$14
  Top 0.406: R14.1 146.5,112.65 D6.1
N$15
  Top 0.5: LED3.C 49,37 49,34.45 R22.2
N$16
  Top 0.406: Q10.B 140.3,106.35 R16.2
N$17
  Top 0.406: Q10.C 143.75,104.15 R17.1
N$18  (via drill 0.6 pad 1.5)
  Top 1: 29.25,23 v29.25,25.75
N$19  (via drill 0.6 pad 1.5)
  Top 1: v48.25,63.25 48.25,66
N$20
  Top 0.5: D2.C 98.3,111.84 R5.2 99.67,112.54 R8.2
N$21  (via drill 0.6 pad 1.5)
  other vias: 127.75,103
N$22  (via drill 0.6 pad 1.5)
  other vias: 124.25,103
N$23  (via drill 0.6 pad 1.5)
  other vias: 113.75,103
N$24  (via drill 0.6 pad 1.5)
  other vias: 110.25,103
N$25
  Top 1.5: R25.1 119.87,128.62 Q7.1
N$26
  Top 1.5: Q6.1 100.85,126.97 R24.1
N$27
  Top 1.5: R23.1 139.87,128.62 Q5.1
N$28  (via drill 0.6 pad 1.5)
  Top 1: v45.75,63.25 45.75,66
N$29  (via drill 0.6 pad 1.5)
  Top 1: v29.25,63.25 29.25,66
N$30  (via drill 0.6 pad 1.5)
  Top 1: v26.75,63.25 26.75,66
N$31
  Top 1: 45.75,23 45.75,25.5
N$32
  Top 1: 26.75,23 26.75,25.5
N$33
  Top 1: R6.2 111,25.39 B1.+
N$34
  Top 0.5: T1.C 101.02,109.48 R5.1
N$36
  Top 1: D8.C 103.7,109.43 T1.B 103.75,110.75 105,112 105.04,112 R8.1
N$37
  Top 0.406: R25.2 119.25,113.5 | 120,113.15 Q8.2 | Q4.E 136.23,113.65 R23.2
  Top 1: 119.25,113.5 120,113.15
  Bottom 0.406: R25.2 119,117
  Bottom 0.5: R23.2 137.5,115.5 138,116
  Bottom 1: R23.2 137.25,115
  pour Bottom (isolate 2, rank 2): 101,119 140,119 140,115 101,115
N$39
  Top 0.5: U$1.4 37.9,50.55 R31.1
N$43
  Top 0.5: U$1.3 39.36,53.09 R32.1
PP1
  Top 0.406: Q8.1 123.05,113.05 124,113 124,113.08 OK2.1 | OK1.3 110.73,115.73 111,116 122,116 122.7,115.2 | 124.73,115.73 125,116 130.2,116 | 133.25,112.55 133.7,112.55 134,112 134,109.45 R13.1 134.2,106.5 | R28.1 133.25,112.55 | 134.2,106.5 134.2,106.4 R3.1 | Q10.E 134.55,106.35 134.2,106.5 | Q4.B 133.55,112.6 133.25,112.55
  Top 1: 122.7,115.2 Q8.1 | OK2.1 124.73,115.73 | R28.1 131.5,114.7 130.2,116
PRECOIL
  Top 3: PRECO1.1 104.62,56 | 104.62,56 105,60 | 104.62,56 L3.2
  pour Bottom (isolate 3, rank 2): 5,96 50,96 64,80 84,80 84,76 110,76 121,60 102,46 93,58 74,58 66,69 58,78 11,78 11,4 5,4
  pour Top (isolate 3): 5,96 43,96 43,79 11,79 11,4 5,4
  pour Top (isolate 3, rank 4): 111,76 117,70 117,56 108,47 100,47 99,48 99,76
SRC1
  Top 1: R14.2 146.5,125.5 146,126
  Bottom 0.406: R29.2 143.54,125
  pour Top (isolate 2): 104,131 146,131 147,130 147,125 146,123 105,123 104,126
  pour Bottom (isolate 2): 104,128 146,128 147,127 147,125 105,125 104,126
V12S
  Top 0.406: C2.+ 117.52,110
  Top 0.5: 113,112.54 OK1.4
  Top 1: C2.+ 115.64,111.64 114.96,112.81 OK1.4 | T1.E 108.48,109.48 109,110 112,110 113,111 113,112.54 | Q8.3 118.35,110.4 118,110 117.52,110
VDD  (via drill 0.6 pad 1.5)  (1 unrouted)
  Top 0.5: 33.09,44.09 C1.+ 32.11,51.11 33,52 33,53 34,54 34,55.52 C17.1 | C17.1 U$1.2 | 24,29 33,29 33,40 33.09,40.09 IC1.1 | v45.25,19.25 45.19,20.19 | 24,32.75 U$2.P$2 | v45,56 51,56 51,65.81 JP1.5 | C17.1 33.89,57.11 v32,59 | v32,63 32,65.81 JP2.5 | JP3.5 24,23.19 | v24.25,19 24.19,19.31
  Top 1: IC1.1 33.09,44.09 | 24,32.75 24,29 24,23.19 | 45.19,20.19 JP4.5 | 24.19,19.31 JP3.5 | v38.75,55.5 36.43,55.5 U$1.2
  Bottom 0.5: v45.25,19.25 44,17 26,17 v24.25,19 | v38.75,55.5 v45,56 | v32,59 v32,63
VSS  (via drill 0.6 pad 1.5)
  Top 0.5: U$1.7 28.68,56 | 24,55.63 23.37,55.63 v23,56 | 24,55.63 U$1.7 | 23.9,53 R9.1 23.9,47.1 24,47 | 23.9,53 23.9,55.53 24,55.63 | 35,42.88 C1.- | U$1.7 C17.2 | 23.9,53 R2.2
  Top 1: IC1.2 35,42.88
  Bottom 0.5: v23,56 v23,61
  pour Bottom (isolate 2): 14,73 58,73 58,13 14,13
  pour Top (isolate 1): 14,73 58,73 58,13 14,13

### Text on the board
Top: MICHAEL5.net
